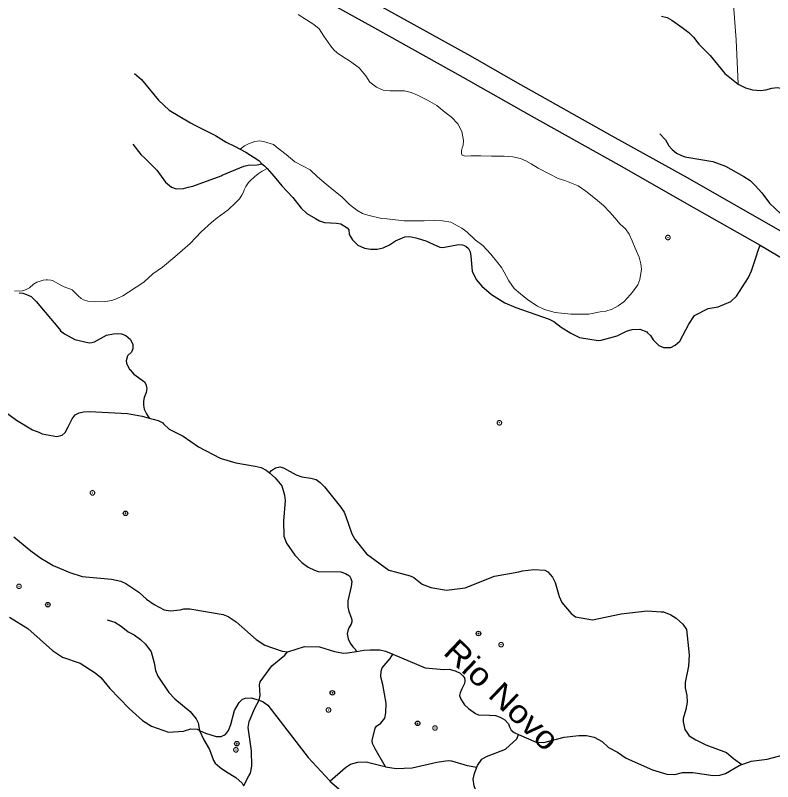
# Model space of a CAD drawing. Extents: x 267.7 to 296, y 7537.7 to 7565.8.
# Drawn here: x 273.164 to 276.501, y 7555.422 to 7558.797 of the extents above; entities that cross this region are included whole.
import ezdxf
from ezdxf.enums import TextEntityAlignment as Align

# ---------------------------------------------------------------- set-up
doc = ezdxf.new("R2010")
doc.units = 0
doc.header["$LTSCALE"] = 0.04
doc.header["$PDMODE"] = 32
doc.header["$PDSIZE"] = 0.02
doc.linetypes.add('SHORT_DASHED', pattern=[2.7, 1.5, -1.2])
for name, color, linetype, lineweight in [('1', 7, 'Continuous', 25), ('21', 7, 'SHORT_DASHED', 13), ('7', 7, 'Continuous', 25)]:
    doc.layers.add(name, color=color, linetype=linetype, lineweight=lineweight)
doc.layers.add('54', color=7, linetype='Continuous')
doc.layers.add('61', color=7, linetype='Continuous')

msp = doc.modelspace()

# ---------------------------------------------------------------- linework, layer by layer
at = {"layer": '1', "lineweight": 13}
msp.add_lwpolyline([(276.3494, 7558.4938), (276.3404, 7558.6888), (276.3258, 7558.8824), (276.3086, 7559.1552), (276.3077, 7559.1752), (276.3058, 7559.1852), (276.3013, 7559.1961), (276.2786, 7559.2252), (276.2413, 7559.2925), (276.2104, 7559.3479), (276.1176, 7559.5316), (276.0331, 7559.6907), (275.9658, 7559.8171), (275.9467, 7559.848), (275.9094, 7559.8989), (275.8394, 7559.988), (275.7994, 7560.0407), (275.7521, 7560.1144), (275.7212, 7560.1535), (275.6703, 7560.2107), (275.6567, 7560.2271), (275.6444, 7560.2424)], dxfattribs=at)
at = {"layer": '1'}
for points in [[(273.5154, 7559.4307), (273.8671, 7559.2348), (274.0918, 7559.1075), (274.4521, 7558.907), (274.7467, 7558.7414), (275.1353, 7558.525), (275.4365, 7558.3553), (275.8235, 7558.1381), (276.1655, 7557.9434), (276.4451, 7557.7853)], [(274.6406, 7558.9119), (275.1689, 7558.6183), (275.3669, 7558.5062), (275.7929, 7558.2667), (276.1242, 7558.0831), (276.5627, 7557.832)], [(276.4451, 7557.7853), (276.6373, 7557.6721), (276.6989, 7557.6363), (276.7557, 7557.6053)]]:
    msp.add_lwpolyline(points, dxfattribs=at)
at = {"layer": '21'}
for points in [[(274.7266, 7558.5031), (274.7081, 7558.5302), (274.6785, 7558.566), (274.6366, 7558.5968), (274.6058, 7558.6165), (274.5824, 7558.6313), (274.5676, 7558.6448), (274.554, 7558.6621), (274.5232, 7558.7052), (274.5023, 7558.7372), (274.4801, 7558.757), (274.4468, 7558.7767), (274.4099, 7558.8001)], [(274.9077, 7558.4575), (274.8794, 7558.4649), (274.8141, 7558.4649), (274.7845, 7558.4674), (274.7549, 7558.4809), (274.7266, 7558.5031)], [(274.1554, 7558.2072), (274.1745, 7558.2222), (274.1918, 7558.232), (274.2201, 7558.2419), (274.2398, 7558.2443), (274.2583, 7558.2419), (274.3014, 7558.2283), (274.3138, 7558.2185), (274.3569, 7558.184), (274.3951, 7558.1519), (274.4629, 7558.1162), (274.4961, 7558.0854), (274.5343, 7558.0534), (274.5676, 7558.0262), (274.6033, 7557.9979), (274.6366, 7557.9634), (274.6686, 7557.9388), (274.6933, 7557.9252), (274.7167, 7557.9166), (274.7771, 7557.903), (274.8017, 7557.9006), (274.8769, 7557.8919), (274.9656, 7557.8919), (275.01, 7557.8932), (275.0457, 7557.8919), (275.0827, 7557.887), (275.1307, 7557.8599), (275.1542, 7557.8426), (275.1899, 7557.8081), (275.2232, 7557.7835), (275.2589, 7557.7453), (275.2897, 7557.7071), (275.3069, 7557.6874), (275.318, 7557.6664), (275.3378, 7557.6282), (275.3624, 7557.5937), (275.3895, 7557.5703), (275.4228, 7557.5444), (275.4647, 7557.5161), (275.4955, 7557.5013), (275.5423, 7557.489), (275.6113, 7557.4816), (275.6902, 7557.4816), (275.7407, 7557.4915), (275.7653, 7557.4951), (275.7937, 7557.5025), (275.8196, 7557.5186), (275.8454, 7557.5358), (275.8615, 7557.5531), (275.8836, 7557.5777), (275.907, 7557.6097), (275.9157, 7557.6344), (275.9231, 7557.6788), (275.9206, 7557.7034), (275.9132, 7557.7317), (275.8947, 7557.7724), (275.8824, 7557.8044), (275.8688, 7557.834), (275.8528, 7557.8574), (275.8294, 7557.8771), (275.8048, 7557.9055), (275.7838, 7557.9301), (275.7555, 7557.9597), (275.721, 7557.9893), (275.6779, 7558.0225), (275.6433, 7558.046), (275.615, 7558.0583), (275.5854, 7558.0694), (275.5559, 7558.0792), (275.5164, 7558.0989), (275.4671, 7558.1236), (275.4376, 7558.1433), (275.4129, 7558.1569), (275.3895, 7558.1667), (275.3562, 7558.1741), (275.318, 7558.1766), (275.2626, 7558.1766), (275.2158, 7558.179), (275.1874, 7558.179), (275.1714, 7558.1778), (275.1455, 7558.1766), (275.1332, 7558.1815), (275.1295, 7558.1889), (275.1295, 7558.2025), (275.1332, 7558.2135), (275.1369, 7558.2259), (275.1381, 7558.2456), (275.1307, 7558.2862), (275.1135, 7558.3195), (275.0864, 7558.3491), (275.0568, 7558.3713), (275.0211, 7558.4008), (274.9804, 7558.4243), (274.936, 7558.4452), (274.9077, 7558.4575)], [(273.1612, 7557.5826), (273.1939, 7557.5837), (273.2097, 7557.5888), (273.2266, 7557.5978), (273.2441, 7557.6131), (273.2593, 7557.6215), (273.274, 7557.6272), (273.287, 7557.6311), (273.3, 7557.6317), (273.3062, 7557.6317), (273.3208, 7557.6311), (273.3282, 7557.6289), (273.3406, 7557.6215), (273.362, 7557.6102), (273.3795, 7557.6018), (273.4145, 7557.5888), (273.4286, 7557.5747), (273.4404, 7557.5623), (273.4545, 7557.5499), (273.4641, 7557.5448), (273.4838, 7557.538), (273.5143, 7557.5352), (273.56, 7557.5363), (273.5899, 7557.5409), (273.613, 7557.5499), (273.6373, 7557.5623), (273.6626, 7557.5781), (273.7298, 7557.6226), (273.7704, 7557.6582), (273.8121, 7557.6875), (273.8668, 7557.7343), (273.9351, 7557.793), (273.9836, 7557.8432), (274.0281, 7557.8855), (274.0541, 7557.9052), (274.1026, 7557.9413), (274.1353, 7557.9724), (274.1522, 7557.9893), (274.1624, 7558.0045), (274.1692, 7558.0186), (274.1725, 7558.0288), (274.1804, 7558.0434), (274.1912, 7558.0604), (274.2002, 7558.0705), (274.2177, 7558.0863), (274.2346, 7558.0998), (274.2521, 7558.1111), (274.2734, 7558.1223)]]:
    msp.add_lwpolyline(points, dxfattribs=at)
for p in [(276.0393, 7557.8186), (275.2971, 7557.0029), (273.5041, 7556.6943), (273.1807, 7556.2827), (275.3044, 7556.0256), (274.544, 7555.7382), (275.0131, 7555.6587), (274.136, 7555.5626)]:
    msp.add_point(p, dxfattribs=at)
at = {"layer": '54'}
for p in [(273.6495, 7556.6043), (273.3077, 7556.2022), (275.2046, 7556.0748), (274.5611, 7555.8134), (274.9365, 7555.6793), (274.14, 7555.5897)]:
    msp.add_point(p, dxfattribs=at)
at = {"layer": '7'}
for points in [[(276.0115, 7558.7933), (276.0353, 7558.7883), (276.0564, 7558.7763), (276.1025, 7558.743), (276.1317, 7558.722), (276.1519, 7558.7007), (276.1755, 7558.6709), (276.2255, 7558.6204), (276.2895, 7558.5405), (276.3494, 7558.4938)], [(273.6886, 7558.5408), (273.7097, 7558.5228), (273.7195, 7558.5144), (273.7946, 7558.4241), (273.8414, 7558.3796), (273.9367, 7558.324), (273.9555, 7558.313), (274.0466, 7558.2684), (274.0935, 7558.2393), (274.1294, 7558.2207), (274.1554, 7558.2072)], [(276.3494, 7558.4938), (276.3815, 7558.4784), (276.4119, 7558.4696), (276.4466, 7558.4661), (276.4711, 7558.4697), (276.4978, 7558.4759), (276.5202, 7558.4792), (276.5378, 7558.4759), (276.5624, 7558.4697), (276.5748, 7558.4615), (276.5881, 7558.442), (276.5996, 7558.4011), (276.61, 7558.3449), (276.6245, 7558.3022), (276.6374, 7558.2787), (276.6893, 7558.2134), (276.7602, 7558.1551), (276.7909, 7558.1351), (276.7944, 7558.134)], [(276.0035, 7558.2756), (276.0287, 7558.2483), (276.043, 7558.2228), (276.0575, 7558.207), (276.077, 7558.1905), (276.0965, 7558.1813), (276.1133, 7558.1738), (276.2366, 7558.1534), (276.2931, 7558.1328), (276.3735, 7558.087), (276.4013, 7558.0694), (276.4233, 7558.0476), (276.4536, 7558.015), (276.4865, 7557.9699), (276.5372, 7557.9233)], [(273.6821, 7558.2304), (273.7172, 7558.185), (273.7356, 7558.1672), (273.7883, 7558.116), (273.8254, 7558.0622), (273.8524, 7558.0401), (273.8732, 7558.0334), (273.9052, 7558.0349), (273.9262, 7558.0399), (273.9461, 7558.0447), (274.0711, 7558.0906), (274.0762, 7558.0928), (274.1704, 7558.133), (274.1906, 7558.1376), (274.2295, 7558.1393), (274.2499, 7558.1433)], [(274.1554, 7558.2072), (274.1797, 7558.1946), (274.2376, 7558.1577), (274.2499, 7558.1433)], [(274.2499, 7558.1433), (274.2623, 7558.1351), (274.2734, 7558.1223)], [(274.2734, 7558.1223), (274.2937, 7558.0989), (274.3115, 7558.078), (274.3382, 7558.0466), (274.3875, 7557.9945), (274.4236, 7557.9487), (274.4492, 7557.9252), (274.4871, 7557.9027), (274.5045, 7557.8929), (274.5265, 7557.8851), (274.5799, 7557.8823), (274.5979, 7557.8783), (274.6268, 7557.8616), (274.6333, 7557.8522), (274.6353, 7557.8313), (274.6496, 7557.8083), (274.6728, 7557.7854), (274.7022, 7557.7716), (274.7295, 7557.7669), (274.7581, 7557.768), (274.7847, 7557.774), (274.8128, 7557.7858), (274.839, 7557.8047), (274.8798, 7557.8218), (274.9027, 7557.8231), (274.9294, 7557.818), (274.9388, 7557.8151), (274.9728, 7557.8045), (275.0056, 7557.7896), (275.0346, 7557.7764), (275.0476, 7557.7751), (275.117, 7557.7887), (275.1337, 7557.7872), (275.1491, 7557.781), (275.1614, 7557.7697), (275.1686, 7557.7564), (275.1716, 7557.7371), (275.1775, 7557.671), (275.1939, 7557.6335), (275.2198, 7557.6046), (275.2624, 7557.5683), (275.3205, 7557.5316), (275.3687, 7557.5111), (275.4572, 7557.4795), (275.5158, 7557.4586), (275.5362, 7557.4486), (275.5695, 7557.4235), (275.611, 7557.3982), (275.6496, 7557.3791), (275.7321, 7557.3653), (275.7448, 7557.3668), (275.8159, 7557.3853), (275.8571, 7557.4059), (275.8817, 7557.4133), (275.9154, 7557.4151), (275.9465, 7557.4028)], [(275.9465, 7557.4028), (275.9467, 7557.4027), (275.95, 7557.3993), (275.9621, 7557.3869), (275.9747, 7557.3675), (275.9996, 7557.3435), (276.0203, 7557.3339), (276.0518, 7557.3349), (276.072, 7557.3449), (276.0912, 7557.3623), (276.131, 7557.437), (276.156, 7557.4747), (276.2163, 7557.5057), (276.261, 7557.5139), (276.3168, 7557.5371), (276.3422, 7557.5607), (276.3943, 7557.6427), (276.4082, 7557.6715), (276.4318, 7557.7476), (276.4344, 7557.7549), (276.4451, 7557.7853)], [(273.1812, 7557.5752), (273.1976, 7557.5737), (273.2141, 7557.5674), (273.2338, 7557.5583), (273.2564, 7557.5377), (273.3582, 7557.4151), (273.3639, 7557.4083), (273.3811, 7557.3952), (273.4261, 7557.3695), (273.4891, 7557.3555), (273.5014, 7557.3561), (273.513, 7557.3591), (273.5265, 7557.3665), (273.5664, 7557.3881), (273.5962, 7557.3942), (273.6136, 7557.3961), (273.632, 7557.394), (273.6515, 7557.3879), (273.6712, 7557.3692), (273.6813, 7557.347), (273.6819, 7557.3283), (273.6756, 7557.3139), (273.6592, 7557.2981), (273.653, 7557.2761), (273.6536, 7557.2655), (273.6674, 7557.2381), (273.6697, 7557.2356), (273.6867, 7557.2167), (273.7338, 7557.1825), (273.7396, 7557.1734), (273.7434, 7557.1533), (273.7413, 7557.136), (273.7321, 7557.1137), (273.7285, 7557.0974), (273.7285, 7557.08), (273.7326, 7557.0625), (273.7429, 7557.042), (273.7544, 7557.0231)], [(273.0017, 7557.0948), (273.0264, 7557.0945), (273.0429, 7557.0913), (273.0948, 7557.0693), (273.1699, 7557.0147), (273.2406, 7556.9724), (273.2675, 7556.961), (273.2829, 7556.9544), (273.3466, 7556.943), (273.3708, 7556.9483)], [(273.3708, 7556.9483), (273.3836, 7556.9605), (273.397, 7556.9845), (273.4149, 7557.021), (273.4286, 7557.0378), (273.4452, 7557.0461), (273.4641, 7557.0513), (273.4911, 7557.0524), (273.6587, 7557.0432), (273.723, 7557.0323), (273.7544, 7557.0231)], [(273.7544, 7557.0231), (273.7716, 7557.0194), (273.7942, 7557.0132), (273.8137, 7557.002), (273.817, 7556.9989), (273.8423, 7556.9752), (273.903, 7556.9433), (273.9713, 7556.8966), (274.0669, 7556.8469), (274.0706, 7556.845), (274.1362, 7556.8263), (274.221, 7556.8125), (274.2479, 7556.8059), (274.27, 7556.7946), (274.284, 7556.7822)], [(274.284, 7556.7822), (274.2923, 7556.7924), (274.3107, 7556.8043), (274.3294, 7556.8088), (274.3455, 7556.8052), (274.4015, 7556.773), (274.4261, 7556.7646), (274.4656, 7556.7584), (274.4891, 7556.7525), (274.5076, 7556.7402), (274.526, 7556.7207), (274.5969, 7556.6324), (274.6133, 7556.6099), (274.6205, 7556.5904), (274.647, 7556.5145), (274.6607, 7556.49), (274.712, 7556.4259), (274.8104, 7556.3541), (274.843, 7556.3453), (274.9031, 7556.329), (274.9197, 7556.3209), (274.9572, 7556.2929), (274.9951, 7556.2778), (275.0632, 7556.2656), (275.146, 7556.2757), (275.2756, 7556.3269), (275.3818, 7556.3471), (275.3994, 7556.3505), (275.449, 7556.3563), (275.4977, 7556.354), (275.5109, 7556.3462), (275.5312, 7556.3237), (275.5426, 7556.3002), (275.5605, 7556.2372), (275.5721, 7556.2115), (275.6136, 7556.1631), (275.6327, 7556.1491), (275.7067, 7556.1353), (275.8338, 7556.1616), (275.9477, 7556.1754), (276.0103, 7556.1705), (276.0199, 7556.1698), (276.0527, 7556.1569), (276.0759, 7556.143), (276.105, 7556.1157), (276.1207, 7556.0933), (276.1331, 7555.9806), (276.13, 7555.9318), (276.1148, 7555.8589), (276.1148, 7555.8354), (276.1224, 7555.8016), (276.1237, 7555.7726), (276.1183, 7555.7404), (276.1064, 7555.701), (276.1059, 7555.686), (276.114, 7555.6528), (276.1246, 7555.6377), (276.1335, 7555.6249), (276.1616, 7555.6073), (276.2061, 7555.5854), (276.2969, 7555.5517), (276.328, 7555.5244), (276.3652, 7555.4978)], [(274.284, 7556.7822), (274.3087, 7556.7603), (274.3377, 7556.7253), (274.3503, 7556.6846), (274.3525, 7556.6601), (274.3457, 7556.5698), (274.3477, 7556.5038), (274.3587, 7556.4723), (274.395, 7556.4199), (274.4264, 7556.3876), (274.4547, 7556.3675), (274.4829, 7556.3533), (274.4988, 7556.3486), (274.5983, 7556.3461), (274.6184, 7556.3399), (274.6359, 7556.3286), (274.6431, 7556.3173), (274.6472, 7556.304), (274.6434, 7556.2813), (274.6289, 7556.2188), (274.6287, 7556.1931), (274.6338, 7556.1726), (274.6441, 7556.1459), (274.6472, 7556.1346), (274.6472, 7556.1264), (274.6441, 7556.1162), (274.6338, 7556.0997), (274.6287, 7556.0864), (274.6266, 7556.0731), (274.6307, 7556.0515), (274.639, 7556.032), (274.6513, 7556.0166), (274.6615, 7556.0063), (274.6679, 7555.9962)], [(273.1584, 7556.5014), (273.2327, 7556.4393), (273.2766, 7556.4072), (273.3022, 7556.392), (273.3311, 7556.3749), (273.405, 7556.344), (273.4591, 7556.3253), (273.5884, 7556.3144)], [(273.5884, 7556.3144), (273.629, 7556.3052), (273.6507, 7556.2959), (273.7084, 7556.2576), (273.7424, 7556.2262), (273.7762, 7556.2024), (273.8201, 7556.1791), (273.8473, 7556.1752), (273.8899, 7556.1788), (273.9072, 7556.1832), (273.9327, 7556.1832), (274.0795, 7556.1586), (274.1023, 7556.1497), (274.1377, 7556.1267), (274.2249, 7556.0493), (274.2638, 7556.0234), (274.3404, 7555.9968), (274.3637, 7555.9943)], [(273.1388, 7556.1467), (273.2194, 7556.0963), (273.3278, 7556.0004), (273.3718, 7555.9706), (273.4494, 7555.9444), (273.5155, 7555.9018), (273.5403, 7555.8812), (273.5813, 7555.8333), (273.6664, 7555.7444), (273.725, 7555.6923), (273.7637, 7555.6673), (273.8392, 7555.6401), (273.9052, 7555.6456), (273.9376, 7555.6555), (273.9659, 7555.6535), (273.9763, 7555.6484)], [(273.5686, 7556.1358), (273.6033, 7556.1255), (273.631, 7556.1069), (273.6619, 7556.0825), (273.688, 7556.0695), (273.7161, 7556.0493), (273.7384, 7556.0278), (273.7625, 7555.9939), (273.7763, 7555.9463), (273.7813, 7555.9122), (273.7927, 7555.8877), (273.8413, 7555.815), (273.8677, 7555.7875), (273.934, 7555.7319), (273.9606, 7555.6993), (273.9697, 7555.681), (273.9763, 7555.6484)], [(274.3637, 7555.9943), (274.3644, 7555.9942), (274.4376, 7556.0178), (274.5041, 7556.0165), (274.5698, 7555.9963), (274.6106, 7555.9889), (274.628, 7555.9893), (274.6679, 7555.9962)], [(274.6679, 7555.9962), (274.7, 7556.0017), (274.7281, 7556.0033), (274.7703, 7556.0024), (274.7958, 7555.9972), (274.8278, 7555.9837)], [(274.2384, 7555.782), (274.2425, 7555.8025), (274.2404, 7555.8484), (274.2436, 7555.8625), (274.2943, 7555.9324), (274.351, 7555.9794), (274.3637, 7555.9943)], [(274.7952, 7555.4885), (274.749, 7555.5668), (274.7384, 7555.5901), (274.7368, 7555.6033), (274.7489, 7555.6587), (274.755, 7555.6673), (274.7749, 7555.6797), (274.7926, 7555.7024), (274.7971, 7555.7255), (274.7977, 7555.7682), (274.7833, 7555.8507), (274.7744, 7555.8841), (274.7758, 7555.9084), (274.7802, 7555.9231), (274.8154, 7555.9646), (274.8278, 7555.9837)], [(274.8278, 7555.9837), (274.9692, 7555.9242), (275.0514, 7555.916), (275.0758, 7555.9173), (275.1024, 7555.9108), (275.1241, 7555.9), (275.1364, 7555.8888), (275.1429, 7555.8791), (275.145, 7555.8667), (275.1429, 7555.8544), (275.1316, 7555.8308), (275.1244, 7555.8134), (275.1214, 7555.8021), (275.1265, 7555.7857), (275.1434, 7555.7616), (275.1614, 7555.7446), (275.1912, 7555.723), (275.2055, 7555.7169), (275.2527, 7555.7159), (275.2795, 7555.7144), (275.3007, 7555.707), (275.3215, 7555.6943), (275.3369, 7555.6769), (275.341, 7555.6645), (275.3492, 7555.6491), (275.3626, 7555.6389), (275.381, 7555.6296)], [(273.9763, 7555.6484), (274.0022, 7555.6358), (274.0497, 7555.6216), (274.0718, 7555.6219), (274.0906, 7555.6304), (274.103, 7555.6479), (274.1142, 7555.675), (274.1297, 7555.7354), (274.1498, 7555.7707), (274.1658, 7555.7858), (274.1783, 7555.7908), (274.2032, 7555.7916), (274.2384, 7555.782)], [(274.1702, 7555.4048), (274.1713, 7555.4063), (274.1936, 7555.448), (274.1997, 7555.4594), (274.2058, 7555.4909), (274.2053, 7555.5587), (274.1908, 7555.6607), (274.1948, 7555.6876), (274.2191, 7555.7468), (274.2384, 7555.782)], [(274.2384, 7555.782), (274.2564, 7555.7747), (274.2766, 7555.7588), (274.4544, 7555.5283), (274.5493, 7555.426), (274.5502, 7555.4252)], [(273.9763, 7555.6484), (273.9954, 7555.6071), (274.0194, 7555.5646), (274.0368, 7555.5161), (274.0447, 7555.5036), (274.0653, 7555.4858), (274.0662, 7555.4849), (274.0939, 7555.4664), (274.1351, 7555.441), (274.163, 7555.4162), (274.1702, 7555.4048)], [(275.1972, 7555.4871), (275.1998, 7555.4943), (275.219, 7555.5213), (275.2403, 7555.5337), (275.324, 7555.5659), (275.3741, 7555.6108), (275.381, 7555.6296)], [(275.381, 7555.6296), (275.4582, 7555.5968), (275.4921, 7555.5943), (275.5818, 7555.6187), (275.6473, 7555.6262), (275.6805, 7555.6251), (275.7147, 7555.6179), (275.7491, 7555.5987), (275.777, 7555.5726), (275.8165, 7555.552), (275.8551, 7555.5253), (275.9717, 7555.4747), (276.0343, 7555.4552), (276.0697, 7555.4541), (276.1039, 7555.4624), (276.1493, 7555.4635), (276.2385, 7555.4497), (276.268, 7555.4518), (276.2927, 7555.4579), (276.3527, 7555.4933), (276.3652, 7555.4978)], [(276.3652, 7555.4978), (276.3985, 7555.5096), (276.4061, 7555.5123), (276.4771, 7555.5219), (276.5479, 7555.5411)], [(274.5502, 7555.4252), (274.6187, 7555.4854), (274.6403, 7555.4994), (274.6729, 7555.5086), (274.7098, 7555.5099), (274.7799, 7555.4922), (274.7939, 7555.4887), (274.7952, 7555.4885)], [(274.7952, 7555.4885), (274.8421, 7555.4801), (274.9131, 7555.4831), (275.0218, 7555.5084), (275.0719, 7555.5155), (275.0865, 7555.5138), (275.155, 7555.4931), (275.1972, 7555.4871)], [(275.1252, 7555.1897), (275.1459, 7555.2451), (275.165, 7555.2615), (275.2118, 7555.2796), (275.2255, 7555.2903), (275.2404, 7555.3094), (275.2456, 7555.3276), (275.2462, 7555.3396), (275.2376, 7555.3559), (275.1998, 7555.3802), (275.19, 7555.3909), (275.1853, 7555.4038), (275.1819, 7555.4337), (275.1867, 7555.4586), (275.1972, 7555.4871)], [(274.5502, 7555.4252), (274.6097, 7555.3727), (274.6592, 7555.323), (274.6713, 7555.3087), (274.7466, 7555.2194), (274.8261, 7555.1805), (274.8465, 7555.1764), (274.8881, 7555.1753), (274.94, 7555.1862), (274.9949, 7555.1977), (275.0152, 7555.197), (275.0665, 7555.1778), (275.1044, 7555.1832), (275.1252, 7555.1897)]]:
    msp.add_lwpolyline(points, dxfattribs=at)

# ---------------------------------------------------------------- texts
at = {"layer": '61', "width": 1.15}
msp.add_text('Rio Novo', height=0.1, rotation=316.264, dxfattribs=at).set_placement((275.2729, 7555.7688), align=Align.CENTER)

doc.saveas('drawing.dxf')
